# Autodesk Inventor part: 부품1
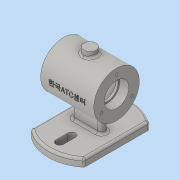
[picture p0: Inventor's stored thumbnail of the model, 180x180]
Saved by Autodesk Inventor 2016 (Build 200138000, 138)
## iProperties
Created: 2017-12
Part Number: 부품1
Material: 일반
Document SubType Name: Modeling
Designer: 605-07
Density: 1 g/cm^3
Appearance: 기본값
Author: 605-07
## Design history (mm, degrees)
sketch "스케치1"
  geometry: L1 (35, 0)-(-35, 0); L2 (35, 30)-(-35, 30); L3 (-35, 30)-(-35, 16); L4 (-35, 16)-(-23, 16); L5 (-23, 16)-(-23, 14); L6 (-23, 14)-(-20, 14); L7 (-20, 14)-(-20, 25); L8 (-20, 25)-(20, 25); L9 (20, 25)-(20, 14); L10 (20, 14)-(23, 14); L11 (23, 14)-(23, 16); L12 (23, 16)-(35, 16); L13 (35, 16)-(35, 30); 1 further point
  constraints: 26 end point, 8 perpendicular, 3 horizontal, 1 midpoint, 1 vertical, 1 vertical alignment
  dimensions: "d1" = 35 distance of L1.start point (0, 0); "d2" = 70 distance of L1.start L1.end; "d3" = 70 distance of L2.start L2.end; "d4" = 12 distance of L3.end L4.end; "d5" = 3 distance of L5.end L6.end; "d7" = 40 distance of L7.end L8.end; "d8" = 3 distance of L9.end L10.end; "d9" = 12 distance of L11.end L12.end; "d10" = 60 diameter of L2 L1; "d11" = 50 diameter of L8 L1; "d12" = 32 diameter of L12 L1; "d13" = 28 diameter of L10 L1; "d14" = 32 diameter of L4 L1; "d15" = 28 diameter of L6 L1
revolve "회전1" sketch "스케치1" stored, may be unused: angle "d16" = 90 deg
node "작업 평면2"
sketch "스케치3"
  geometry: L1 (-35, -42.426)-(35, -42.426); L2 (35, -42.426)-(35, 42.426); L3 (35, 42.426)-(-35, 42.426); L4 (-35, 42.426)-(-35, -42.426); L5 (-35, -42.426)-(35, 42.426); L6 (35, -42.426)-(-35, 42.426); A1 r 55 centre (0, 0) between (-35, -42.426) and (35, -42.426); A2 r 55 centre (0, 0) between (35, 42.426) and (-35, 42.426); 1 further point
  constraints: 12 end point, 4 point on circle, 2 centre point, 2 midpoint, 2 parallel, 1 coincident, 1 horizontal, 1 perpendicular
  dimensions: "d27" = 70 distance of L2.end L3.end; "d28" = 55 radius of A2
extrude "돌출1" join sketch "스케치3" distance "d29" = 10; taper "d30" = 0 deg
sketch "스케치4"
  geometry: L1 (-15, 0)-(15, 0); L2 (-15, -5)-(15, -5); L3 (15, 5)-(-15, 5); A1 r 5 centre (-15, 0) between (-15, 5) and (-15, -5); A2 r 5 centre (15, 0) between (15, -5) and (15, 5); 2 further points
  constraints: 8 end point, 4 point on circle, 4 tangent, 2 centre point, 1 coincident, 1 horizontal, 1 midpoint, 1 parallel
  dimensions: "d31" = 5 radius of A2; "d32" = 30 distance of L3.start L3.end
extrude "돌출2" join sketch "스케치4" stored distance "d33" = 10; taper "d34" = 0 deg
node "작업 평면3"
sketch "스케치5"
  geometry: C1 r 8 at (0, 0); 1 further point
  constraints: 1 centre point, 1 coincident
  dimensions: "d36" = 16 diameter of C1
extrude "돌출3" join sketch "스케치5" stored distance "d37" = 10; taper "d38" = 0 deg
node "작업 평면4"
sketch "스케치6"
  geometry: L1 (-35, 30)-(-35, -30) reference; L2 (35, 30)-(-35, 30) reference; 2 further points
  constraints: 1 other
  dimensions: "d39" = 35 distance from line of L1 point (0, 0); "d40" = 30 distance from line of L2 point (0, 0)
feature "엠보싱1" sketch "스케치6" dims "d41" = 0.5, "d42" = 0
fillet "모깎기1" dims "d43" = 3
fillet "모깎기2" dims "d44" = 3
fillet "모깎기3" dims "d45" = 3
sketch "스케치7"
  geometry: L1 (0, 40)-(0, 24); L2 (-5, 40)-(-5, 24); L3 (5, 24)-(5, 40); A1 r 5 centre (0, 40) between (5, 40) and (-5, 40); A2 r 5 centre (0, 24) between (-5, 24) and (5, 24); 2 further points
  constraints: 8 end point, 4 point on circle, 4 tangent, 2 centre point, 1 midpoint, 1 parallel, 1 vertical, 1 vertical alignment
  dimensions: "d46" = 5 radius of A1; "d47" = 16 distance of L3.start L3.end; "d48" = 32 distance of point (0, 0) point (0, 32)
extrude "돌출4" cut sketch "스케치7" stored distance "d49" = 10; taper "d50" = 0 deg
sketch "스케치8" dims "d51" = 46
  geometry: 3 further points
  constraints: 2 horizontal alignment, 1 coincident, 2 other
hole "구멍1" sketch "스케치8" at (-23, 0) diameter "d52" = 3.242; stored, may be unused: countersink angle "d56" = 90 deg, drill point angle "d58" = 120 deg; dims "d53" = 8, "d54" = 4, "d55" = 2, "d57" = 10
node "솔리드1"
mirror "대칭1"
pattern_circular "원형 패턴1" dims angle "d60" = 360 deg
mirror "대칭2"
other parameters: "d23" = -62, "d35" = 37
